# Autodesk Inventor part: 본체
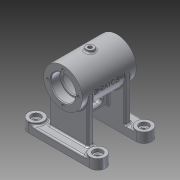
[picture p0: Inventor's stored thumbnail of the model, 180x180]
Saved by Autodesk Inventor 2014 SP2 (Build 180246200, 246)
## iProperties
Created: 2015-11
Part Number: 본체
Material: 알루미늄 6061
Document SubType Name: Modeling
Designer: 702
Density: 2.71 g/cm^3
Appearance: 알루미늄 - 평지
Mass: 360.649 g
Surface Area: 456.894 cm^2
Volume: 133.081 cm^3
Author: 702
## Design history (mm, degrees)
sketch "스케치1"
  geometry: L1 (-35, 25)-(35, 25); L2 (-35, 25)-(-35, 16); L3 (-35, 16)-(-23, 16); L4 (-23, 16)-(-23, 14); L5 (-23, 14)-(-21, 14); L6 (-21, 14)-(-21, 21); L7 (-21, 21)-(21, 21); L8 (21, 21)-(21, 14); L9 (21, 14)-(23, 14); L10 (23, 14)-(23, 16); L11 (23, 16)-(35, 16); L12 (35, 16)-(35, 25); L13 (-32.029, 0)-(31.894, 0); L14 (-49, 0)-(49, 0) reference; 1 further point
  constraints: 26 end point, 7 parallel, 3 perpendicular, 1 collinear, 1 horizontal, 1 point on line, 1 vertical
  dimensions: "d0" = 25 distance between parallel lines of L13 L1; "d1" = 16 distance from line of L13.end L11; "d2" = 21 distance from line of point (0, 0) L7; "d3" = 16 distance from line of point (0, 0) L3; "d4" = 70 distance between parallel lines of L12 L2; "d5" = 35 distance from line of point (0, 0) L2; "d6" = 12 distance between parallel lines of L4 L2; "d7" = 12 distance between parallel lines of L10 L12; "d8" = 42 distance between parallel lines of L8 L6; "d9" = 21 distance from line of point (0, 0) L6; "d10" = 14 distance from line of point (0, 0) L5; "d11" = 14 distance from line of point (0, 0) L9
revolve "회전1" sketch "스케치1" stored, may be unused: angle "d12" = 90 deg
node "작업 평면1"
sketch "스케치2"
  geometry: L1 (-25, 0)-(-25, -68); L2 (25, 0)-(25, -68); L3 (-25, -68)-(25, -68); A1 r 25 centre (0, 0) between (-25, 0) and (25, 0) reference; A2 r 25 centre (0, 0) between (-25, 0) and (25, 0); 1 further point
  constraints: 6 end point, 4 point on circle, 2 tangent, 1 centre point, 1 coincident, 1 concentric, 1 parallel, 1 vertical
  dimensions: "d14" = 68 distance of L1.start L1.end; "d15" = 68 distance of L2.start L2.end
extrude "돌출1" join sketch "스케치2" distance "d16" = 8; taper "d17" = 0 deg
sketch "스케치3"
  geometry: L1 (0, 0)-(50, 0) reference; L2 (50, 0)-(50, 8) reference; L3 (0, 8)-(50, 8) reference; L4 (0, 0)-(0, 8) reference; L5 (-15, 0)-(65, 0); L6 (-15, 20)-(65, 20); A1 r 10 centre (-15, 10) between (-15, 0) and (-15, 20); A2 r 10 centre (65, 10) between (65, 0) and (65, 20); 1 further point
  constraints: 4 end point, 4 point on circle, 4 tangent, 2 centre point, 1 collinear
  dimensions: "d18" = 20 diameter of A1; "d19" = 20 diameter of A2; "d20" = 80 distance of A2.centre A1.centre; "d21" = 40 horizontal distance of point (25, -20) A1.centre
extrude "돌출2" join sketch "스케치3" distance "d22" = 10; taper "d23" = 0 deg
extrude "돌출3" join sketch "스케치3" distance "d24" = 13; taper "d25" = 0 deg
sketch "스케치4"
  geometry: C1 r 10 at (0, 0) reference; 2 further points
  constraints: 1 coincident
node "작업 평면2"
sketch "스케치5"
  geometry: L1 (80, -13)-(80, 0); L2 (90, 0)-(80, 0) reference; L3 (90, 0)-(90, -13) reference; L4 (83, 0)-(83, -9); L5 (83, -9)-(86, -9); L6 (86, -9)-(86, -13); L7 (70, -13)-(90, -13) reference; L8 (86, -13)-(80, -13); L9 (83, 0)-(80, 0); L10 (80, -13)-(80, 0); 1 further point
  constraints: 14 end point, 3 parallel, 2 collinear, 2 point on line, 1 perpendicular, 1 vertical
  dimensions: "d27" = 10 distance between parallel lines of L3 L1; "d28" = 3 distance between parallel lines of L1 L4; "d29" = 6 distance between parallel lines of L1 L6; "d30" = 4 distance between parallel lines of L7 L5
revolve "회전2" sketch "스케치5" stored, may be unused: angle "d31" = 90 deg
sketch "스케치6"
  geometry: L1 (21, -21)-(-21, -21) reference; L2 (-20, -58)-(-20, 0) reference; L3 (20, -58)-(20, 0) reference; L4 (-20, -45)-(20, -45); L5 (20, -45)-(20, -21); L6 (-20, -21)-(-20, -45); L7 (-20, -21)-(20, -21); L8 (-35, -25)-(35, -25) reference; 1 further point
  constraints: 8 end point, 6 point on line, 2 collinear, 1 perpendicular
  dimensions: "d32" = 20 distance between parallel lines of L4 L8
extrude "돌출4" join sketch "스케치6" stored distance "d33" = 8; taper "d34" = 0 deg
sketch "스케치7"
  geometry: L1 (68, 20)-(68, 40) reference; L2 (31.5, 8)-(31.5, -8); L3 (38.5, 8)-(38.5, -8); L4 (25, 35)-(-25, 35) reference; A1 r 3.5 centre (35, 8) between (31.5, 8) and (38.5, 8); A2 r 3.5 centre (35, -8) between (31.5, -8) and (38.5, -8); 1 further point
  constraints: 4 end point, 4 point on circle, 4 tangent, 2 centre point
  dimensions: "d35" = 7 diameter of A1; "d36" = 7 diameter of A2; "d37" = 33 distance from line of L1 A1.centre; "d38" = 33 distance from line of L1 A2.centre (= d37); "d39" = 16 distance of A2.centre A1.centre; "d40" = 27 distance from line of A1.centre L4
extrude "돌출5" cut sketch "스케치7" distance "d41" = 8; taper "d42" = 0 deg
sketch "스케치8"
  geometry: C1 r 16 at (0, 0) reference; 1 further point
  constraints: 1 vertical alignment
  dimensions: "d43" = 20 distance of C1.centre point (0, 20)
hole "구멍1" sketch "스케치8" at (0, 20) diameter "d44" = 3.242; stored, may be unused: countersink angle "d48" = 90 deg, drill point angle "d50" = 118 deg; dims "d45" = 8, "d46" = 4, "d47" = 2, "d49" = 10
chamfer "모따기1" distance "d54" = 1; stored, may be unused: second distance "d55" = 2, angle "d56" = 45 deg
chamfer "모따기2" distance "d57" = 1; stored, may be unused: second distance "d58" = 2, angle "d59" = 45 deg
chamfer "모따기3" distance "d60" = 3; stored, may be unused: second distance "d61" = 2, angle "d62" = 45 deg
chamfer "모따기4" distance "d63" = 3; stored, may be unused: second distance "d64" = 2, angle "d65" = 45 deg
chamfer "모따기5" distance "d66" = 1; stored, may be unused: second distance "d67" = 2, angle "d68" = 45 deg
fillet "모깎기1" dims "d69" = 0.3
fillet "모깎기2" dims "d70" = 0.3
fillet "모깎기3" dims "d71" = 0.3
fillet "모깎기4" dims "d72" = 0.3
fillet "모깎기5" dims "d73" = 2
fillet "모깎기6" dims "d74" = 2
fillet "모깎기7" dims "d75" = 2
fillet "모깎기8" dims "d76" = 2
fillet "모깎기9" dims "d77" = 2
fillet "모깎기10" dims "d78" = 2
fillet "모깎기11" dims "d79" = 2
fillet "모깎기12" dims "d80" = 2
fillet "모깎기13" dims "d81" = 2
fillet "모깎기14" dims "d82" = 2
node "작업 평면4"
sketch "스케치9"
  geometry: C1 r 5 at (0, 0); 1 further point
  constraints: 1 centre point, 1 coincident
  dimensions: "d84" = 10 diameter of C1
extrude "돌출6" join sketch "스케치9" stored distance "d85" = 8; taper "d86" = 0 deg
sketch "스케치10"
  geometry: 2 further points
  constraints: 1 coincident
hole "구멍2" sketch "스케치10" at (0, 0) diameter "d87" = 4.917; stored, may be unused: countersink angle "d91" = 90 deg, drill point angle "d93" = 118 deg; dims "d88" = 15, "d89" = 4, "d90" = 2, "d92" = 15
sketch "스케치11"
  geometry: L1 (0, 0)-(-14, -24.249); L2 (0, 0)-(-57.632, 0)
  constraints: 4 end point, 1 horizontal
  dimensions: "d94" = 60 deg angle of L2 L1; "d95" = 28 distance of L1.start L1.end
node "작업 평면5"
fillet "모깎기16" dims "d107" = 2
node "작업 평면6"
sketch "스케치15"
  geometry: L1 (0, 0)-(57.811, 0); L2 (0, 0)-(14, -24.249)
  constraints: 4 end point, 1 horizontal
  dimensions: "d109" = 60 deg angle of L1 L2; "d110" = 28 distance of L1.start L2.end
node "작업 평면8"
sketch "스케치16"
  geometry: C1 r 5 at (0, 0); 1 further point
  constraints: 1 centre point, 1 coincident
  dimensions: "d111" = 10 diameter of C1
extrude "돌출8" join sketch "스케치16" stored distance "d112" = 8; taper "d113" = 0 deg
sketch "스케치17"
  geometry: C1 r 5 at (0, 0) reference; 1 further point
  constraints: 1 coincident
hole "구멍4" sketch "스케치17" at (0, 0) diameter "d114" = 4.917; stored, may be unused: countersink angle "d118" = 90 deg, drill point angle "d120" = 118 deg; dims "d115" = 15, "d116" = 4, "d117" = 2, "d119" = 15
sketch "스케치18"
  geometry: L1 (-20.592, 2.487)-(20.887, 2.487); L2 (20.887, 2.487)-(20.887, -3.517); L3 (20.887, -3.517)-(-20.592, -3.517); L4 (-20.592, -3.517)-(-20.592, 2.487); L5 (35, -25)-(35, 25) reference; L6 (-35, 25)-(35, 25) reference; 1 further point
  constraints: 2 other
  dimensions: "d121" = 35 distance from line of L5 point (0, 0) (derived); "d122" = 25 distance from line of L6 point (0, 0) (derived)
feature "엠보싱1" sketch "스케치18" dims "d123" = 0.5, "d124" = 0
fillet "모깎기17" dims "d125" = 2
node "솔리드1"
mirror "대칭1"
pattern_circular "원형 패턴1" dims angle "d52" = 360 deg
mirror "대칭3"
mirror "대칭4"
other parameters: "d83" = 28, "d108" = 25
